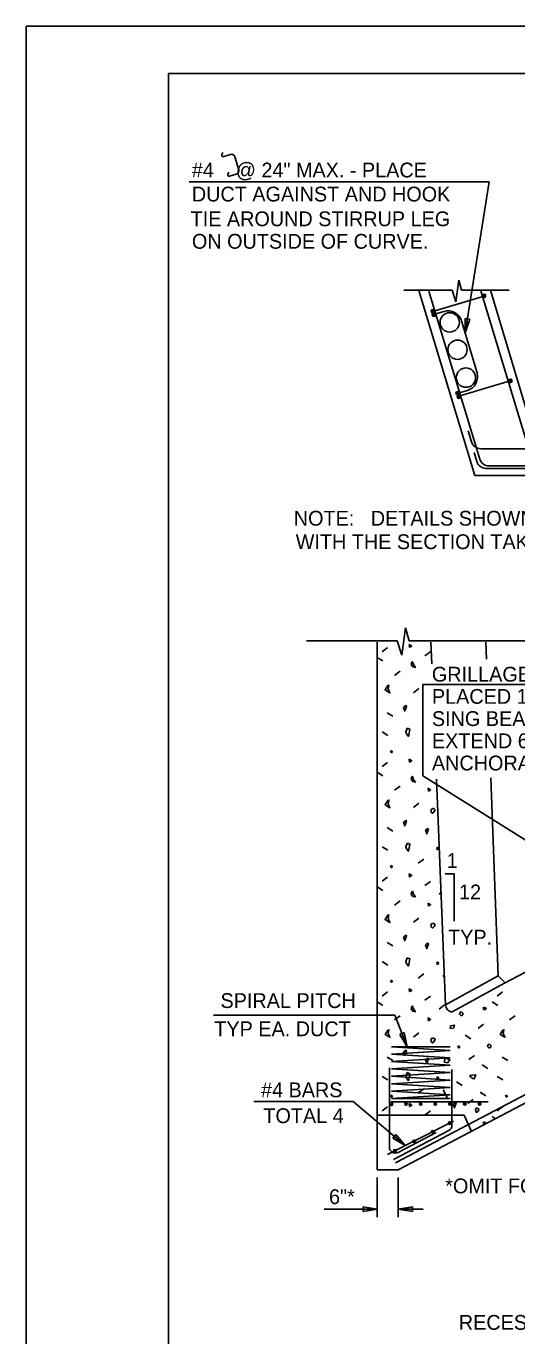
# Model space of a CAD drawing. Extents: x 0 to 22.7, y 0 to 15.7.
# Drawn here: x 0 to 3.45, y 5.45 to 14.67 of the extents above; entities that cross this region are included whole.
import ezdxf

# ---------------------------------------------------------------- set-up
doc = ezdxf.new("R2010")
doc.units = 0
for name, color, linetype in [('BORDER_ANNO_Cutsheet', 7, 'Continuous'), ('BRDG_ANNO_Anno-Sheet', 7, 'Continuous'), ('BRDG_ANNO_General-Notes', 7, 'Continuous'), ('BRDG_BASE_Dtlctrln', 7, 'Continuous'), ('BRDG_BASE_Obj-Line', 7, 'Continuous'), ('BRDG_BASE_Pattern', 7, 'Continuous'), ('BRDG_BASE_Rebar', 7, 'Continuous')]:
    doc.layers.add(name, color=color, linetype=linetype)

msp = doc.modelspace()

# ---------------------------------------------------------------- linework, layer by layer
at = {"layer": 'BORDER_ANNO_Cutsheet'}
msp.add_lwpolyline([(0, 14.6667), (22.6667, 14.6667), (22.6667, 0), (0, 0)], close=True, dxfattribs=at)
at = {"layer": 'BRDG_ANNO_Anno-Sheet'}
msp.add_lwpolyline([(1, 14.3333), (22.3333, 14.3333), (22.3333, 0.3333), (1, 0.3333)], close=True, dxfattribs=at)
at = {"layer": 'BRDG_ANNO_General-Notes'}
for p, q in [((3.2552, 13.5712), (1.147, 13.5712)), ((3.0872, 12.5074), (3.2552, 13.5712)), ((3.0863, 12.6087), (3.1193, 12.6036)), ((3.0872, 12.5074), (3.0863, 12.6087)), ((3.1193, 12.6036), (3.0872, 12.5074)), ((6.0675, 10.0336), (2.7891, 10.0336)), ((2.7891, 10.0336), (2.7891, 9.3907)), ((4.5997, 8.2579), (2.7891, 9.3907)), ((2.9479, 8.7018), (3.0094, 8.7018)), ((3.0094, 8.3667), (3.0094, 8.7018)), ((1.3162, 7.7056), (2.5928, 7.7056)), ((2.5928, 7.7056), (2.6797, 7.4839)), ((2.6277, 7.5709), (2.6587, 7.5831)), ((2.6797, 7.4839), (2.6277, 7.5709)), ((2.6587, 7.5831), (2.6797, 7.4839)), ((2.2988, 7.0975), (1.6005, 7.0975)), ((2.665, 6.788), (2.2988, 7.0975)), ((2.5779, 6.8398), (2.5994, 6.8653)), ((2.665, 6.788), (2.5779, 6.8398)), ((2.5994, 6.8653), (2.665, 6.788)), ((2.4694, 6.5646), (2.4694, 6.2837)), ((2.6161, 6.5646), (2.6161, 6.2837)), ((2.4694, 6.3399), (2.0948, 6.3399)), ((2.3694, 6.3233), (2.3694, 6.3566)), ((2.3694, 6.3566), (2.4694, 6.3399)), ((2.4694, 6.3399), (2.3694, 6.3233)), ((2.6161, 6.3399), (2.7161, 6.3566)), ((2.7909, 6.3399), (2.6161, 6.3399)), ((2.7161, 6.3233), (2.6161, 6.3399)), ((2.7161, 6.3566), (2.7161, 6.3233))]:
    msp.add_line(p, q, dxfattribs=at)
at = {"layer": 'BRDG_BASE_Dtlctrln'}
msp.add_line((2.5405, 6.7252), (3.0046, 6.9592), dxfattribs=at)
at = {"layer": 'BRDG_BASE_Obj-Line'}
for p, q in [((3.0218, 12.7276), (3.0421, 12.8803)), ((3.0421, 12.8803), (3.0627, 12.808)), ((2.9958, 12.808), (2.6553, 12.808)), ((2.7614, 12.8061), (3.1561, 11.5048)), ((2.9958, 12.808), (3.0218, 12.7276)), ((3.3959, 12.808), (3.0627, 12.808)), ((3.3192, 12.808), (3.0627, 12.808)), ((3.2652, 12.808), (3.5786, 11.7597)), ((3.1561, 11.5048), (4.3145, 11.5048)), ((2.6414, 10.2406), (2.6669, 10.4317)), ((2.6669, 10.4317), (2.6926, 10.3412)), ((2.6089, 10.3412), (1.9724, 10.3412)), ((2.4694, 6.6182), (2.4694, 10.332)), ((2.6089, 10.3412), (2.6414, 10.2406)), ((3.5639, 10.3412), (2.6926, 10.3412)), ((2.8459, 10.332), (2.8521, 10.1792)), ((3.2372, 10.2127), (3.2329, 10.3313)), ((2.885, 9.368), (2.9494, 7.779)), ((3.3196, 7.983), (3.2681, 9.3773)), ((4.8611, 8.7151), (3.3593, 7.9299)), ((2.6161, 6.6182), (6.0466, 8.4231)), ((2.9494, 7.779), (3.3184, 7.983)), ((2.996, 7.7291), (3.3593, 7.9299)), ((3.3658, 7.9356), (3.3184, 7.983)), ((2.4694, 7.0027), (3.0794, 7.0027)), ((3.0794, 7.0027), (3.1307, 6.8914)), ((2.4694, 6.6182), (2.6161, 6.6182))]:
    msp.add_line(p, q, dxfattribs=at)
for centre in [(2.9788, 12.5819), (3.0335, 12.3899), (3.0931, 12.193)]:
    msp.add_circle(centre, 0.068, dxfattribs=at)
msp.add_arc((3.0003, 7.779), 0.0509, 180.0392, 265.73939, dxfattribs=at)
at = {"layer": 'BRDG_BASE_Pattern'}
for p, q in [((2.5413, 10.2934), (2.5028, 10.2641)), ((2.843, 10.2639), (2.8045, 10.2345)), ((2.4694, 10.2241), (2.509, 10.1991)), ((2.6296, 10.1261), (2.5911, 10.0968)), ((2.7616, 10.0052), (2.7231, 9.9759)), ((2.5398, 9.8346), (2.5794, 9.8098)), ((2.5039, 9.6994), (2.5434, 9.6744)), ((2.4694, 9.4161), (2.509, 9.3911)), ((2.5413, 9.4854), (2.5028, 9.4561)), ((2.6296, 9.3182), (2.5911, 9.2889)), ((2.7616, 9.1972), (2.7231, 9.1679)), ((2.5398, 9.0267), (2.5794, 9.0018)), ((2.5039, 8.8915), (2.5434, 8.8664)), ((2.7964, 8.8045), (2.7579, 8.7752)), ((2.5413, 8.6774), (2.5028, 8.6482)), ((2.4694, 8.6082), (2.509, 8.5832)), ((2.843, 8.6479), (2.8045, 8.6186)), ((2.6296, 8.5102), (2.5911, 8.4809)), ((2.9174, 8.5677), (2.904, 8.5574)), ((2.7616, 8.3893), (2.7231, 8.36)), ((2.5398, 8.2187), (2.5794, 8.1939)), ((2.5039, 8.0835), (2.5434, 8.0584)), ((2.7964, 7.9965), (2.7579, 7.9672)), ((2.9336, 7.9876), (2.9416, 7.9716)), ((2.5413, 7.8695), (2.5028, 7.8402)), ((2.843, 7.8399), (2.8045, 7.8107)), ((3.3501, 7.8695), (3.3116, 7.8402)), ((2.4694, 7.8003), (2.509, 7.7753)), ((2.9424, 7.7787), (2.904, 7.7494)), ((3.2782, 7.8003), (3.3178, 7.7753)), ((2.6296, 7.7022), (2.5911, 7.673)), ((3.4384, 7.7022), (3.3999, 7.673)), ((2.7616, 7.5813), (2.7231, 7.552)), ((3.087, 7.5656), (3.1267, 7.5406)), ((3.2174, 7.6425), (3.179, 7.6132)), ((2.5398, 7.4107), (2.5794, 7.3859)), ((3.1526, 7.4227), (3.1141, 7.3934)), ((3.3486, 7.4107), (3.3881, 7.3859)), ((3.2077, 7.3561), (3.2473, 7.3311)), ((2.5039, 7.2755), (2.5434, 7.2505)), ((3.0276, 7.2363), (3.0672, 7.2112)), ((3.3127, 7.2755), (3.3522, 7.2505)), ((2.7964, 7.1885), (2.7579, 7.1593)), ((2.9336, 7.1797), (2.963, 7.1208)), ((3.1443, 7.1135), (3.1058, 7.0842)), ((3.1927, 7.1641), (3.2323, 7.1391)), ((2.5413, 7.0616), (2.5028, 7.0322)), ((2.843, 7.032), (2.8045, 7.0027)), ((3.3501, 7.0616), (3.3116, 7.0322)), ((3.2782, 6.9923), (3.2985, 6.9795))]:
    msp.add_line(p, q, dxfattribs=at)
for points in [[(2.6936, 10.316), (2.6966, 10.2953), (2.7114, 10.3042)], [(2.7116, 10.1906), (2.7083, 10.174), (2.7193, 10.1578), (2.7378, 10.1542), (2.723, 10.1736), (2.7167, 10.1939)], [(2.5443, 10.0255), (2.5237, 9.9947), (2.5583, 9.974), (2.5457, 10.002), (2.551, 10.0277)], [(2.6538, 9.8728), (2.6629, 9.8462), (2.6629, 9.8491), (2.6747, 9.8787), (2.6717, 9.8846)], [(2.6797, 9.7253), (2.6707, 9.6988), (2.6753, 9.6856), (2.6885, 9.6679), (2.6944, 9.6915), (2.6989, 9.718)], [(2.5665, 9.567), (2.5628, 9.5589), (2.5671, 9.5544), (2.5724, 9.5544), (2.5746, 9.5568), (2.5746, 9.5611), (2.5739, 9.5632), (2.5716, 9.5656)], [(2.6936, 9.508), (2.6966, 9.4873), (2.7114, 9.4962)], [(2.7116, 9.3827), (2.7083, 9.366), (2.7193, 9.3498), (2.7378, 9.3462), (2.723, 9.3657), (2.7167, 9.3859)], [(2.5443, 9.2176), (2.5237, 9.1867), (2.5583, 9.166), (2.5457, 9.194), (2.551, 9.2197)], [(2.8269, 9.3034), (2.8299, 9.2828), (2.8447, 9.2917)], [(2.8482, 9.157), (2.8482, 9.1347), (2.8583, 9.1275), (2.8614, 9.1304), (2.8701, 9.1393), (2.8759, 9.1511), (2.8717, 9.157), (2.8657, 9.1598), (2.8629, 9.1598), (2.8571, 9.1582)], [(2.6538, 9.0648), (2.6629, 9.0383), (2.6629, 9.0411), (2.6747, 9.0707), (2.6717, 9.0766)], [(2.8076, 9.0083), (2.8167, 8.9817), (2.8167, 8.9846), (2.8284, 9.0142), (2.8255, 9.0201)], [(2.6797, 8.9174), (2.6707, 8.8908), (2.6753, 8.8776), (2.6885, 8.8599), (2.6944, 8.8835), (2.6989, 8.9101)], [(2.888, 8.8796), (2.8904, 8.8722), (2.8925, 8.8722), (2.8955, 8.8729), (2.8977, 8.8751), (2.8998, 8.8796), (2.8992, 8.884), (2.8955, 8.8847), (2.8939, 8.8863), (2.891, 8.8863)], [(2.5665, 8.7591), (2.5628, 8.7509), (2.5671, 8.7465), (2.5724, 8.7465), (2.5746, 8.7488), (2.5746, 8.7531), (2.5739, 8.7553), (2.5716, 8.7577)], [(2.6936, 8.7001), (2.6966, 8.6794), (2.7114, 8.6883)], [(2.7116, 8.5747), (2.7083, 8.5581), (2.7193, 8.5419), (2.7378, 8.5382), (2.723, 8.5578), (2.7167, 8.578)], [(2.8269, 8.4955), (2.8299, 8.4748), (2.8447, 8.4837)], [(2.5443, 8.4096), (2.5237, 8.3788), (2.5583, 8.358), (2.5457, 8.386), (2.551, 8.4118)], [(2.8482, 8.3491), (2.8482, 8.3267), (2.8583, 8.3195), (2.8614, 8.3224), (2.8701, 8.3313), (2.8759, 8.3431), (2.8717, 8.3491), (2.8657, 8.3519), (2.8629, 8.3519), (2.8571, 8.3503)], [(2.6538, 8.2569), (2.6629, 8.2303), (2.6629, 8.2332), (2.6747, 8.2628), (2.6717, 8.2686)], [(2.8076, 8.2003), (2.8167, 8.1738), (2.8167, 8.1766), (2.8284, 8.2062), (2.8255, 8.2121)], [(2.6797, 8.1094), (2.6707, 8.0829), (2.6753, 8.0696), (2.6885, 8.0519), (2.6944, 8.0755), (2.6989, 8.1021)], [(2.888, 8.0716), (2.8904, 8.0642), (2.8925, 8.0642), (2.8955, 8.065), (2.8977, 8.0671), (2.8998, 8.0716), (2.8992, 8.076), (2.8955, 8.0768), (2.8939, 8.0783), (2.891, 8.0783)], [(2.5665, 7.9511), (2.5628, 7.943), (2.5671, 7.9385), (2.5724, 7.9385), (2.5746, 7.9408), (2.5746, 7.9452), (2.5739, 7.9473), (2.5716, 7.9497)], [(2.6936, 7.8921), (2.6966, 7.8715), (2.7114, 7.8803)], [(2.7116, 7.7668), (2.7083, 7.7502), (2.7193, 7.7339), (2.7378, 7.7303), (2.723, 7.7498), (2.7167, 7.7701)], [(3.2171, 7.7623), (3.2164, 7.7466), (3.2259, 7.7443), (3.2352, 7.755)], [(2.8269, 7.6875), (2.8299, 7.6669), (2.8447, 7.6757)], [(3.0547, 7.7291), (3.0473, 7.7129), (3.056, 7.7039), (3.0666, 7.7039), (3.0709, 7.7086), (3.0709, 7.7172), (3.0695, 7.7215), (3.0649, 7.7262)], [(2.5443, 7.6017), (2.5237, 7.5708), (2.5583, 7.5501), (2.5457, 7.5781), (2.551, 7.6038)], [(2.9852, 7.6302), (2.9822, 7.6126), (3.0029, 7.6155), (3.0087, 7.6184), (3.0117, 7.6361)], [(3.3531, 7.6017), (3.3325, 7.5708), (3.3671, 7.5501), (3.3545, 7.5781), (3.3598, 7.6038)], [(2.8482, 7.5411), (2.8482, 7.5187), (2.8583, 7.5116), (2.8614, 7.5145), (2.8701, 7.5233), (2.8759, 7.5352), (2.8717, 7.5411), (2.8657, 7.5439), (2.8629, 7.5439), (2.8571, 7.5423)], [(3.04, 7.4896), (3.0363, 7.4815), (3.0406, 7.477), (3.0459, 7.477), (3.0481, 7.4793), (3.0481, 7.4836), (3.0473, 7.4858), (3.0451, 7.4881)], [(3.2516, 7.5021), (3.2442, 7.4859), (3.2528, 7.4769), (3.2634, 7.4769), (3.2678, 7.4816), (3.2678, 7.4903), (3.2663, 7.4945), (3.2617, 7.4993)], [(2.6538, 7.449), (2.6629, 7.4223), (2.6629, 7.4252), (2.6747, 7.4548), (2.6717, 7.4607)], [(2.8076, 7.3924), (2.8167, 7.3658), (2.8167, 7.3686), (2.8284, 7.3983), (2.8255, 7.4042)], [(2.9446, 7.4065), (2.9432, 7.3748), (2.9623, 7.3703), (2.9807, 7.3917)], [(2.6797, 7.3015), (2.6707, 7.2749), (2.6753, 7.2617), (2.6885, 7.244), (2.6944, 7.2676), (2.6989, 7.2941)], [(3.1394, 7.2839), (3.1218, 7.2824), (3.1218, 7.2736), (3.1409, 7.2604), (3.1513, 7.2589), (3.1616, 7.2868)], [(2.888, 7.2636), (2.8904, 7.2562), (2.8925, 7.2562), (2.8955, 7.257), (2.8977, 7.2592), (2.8998, 7.2636), (2.8992, 7.2681), (2.8955, 7.2688), (2.8939, 7.2704), (2.891, 7.2704)], [(2.5665, 7.1431), (2.5628, 7.1351), (2.5671, 7.1305), (2.5724, 7.1305), (2.5746, 7.1329), (2.5746, 7.1372), (2.5739, 7.1394), (2.5716, 7.1417)], [(3.3753, 7.1431), (3.3716, 7.1351), (3.3759, 7.1305), (3.3812, 7.1305), (3.3834, 7.1329), (3.3834, 7.1372), (3.3827, 7.1394), (3.3804, 7.1417)], [(2.6936, 7.0842), (2.6966, 7.0635), (2.7114, 7.0724)], [(3.0024, 7.0798), (3.0116, 7.0532), (3.0116, 7.0561), (3.0233, 7.0857), (3.0203, 7.0916)], [(3.1597, 7.0384), (3.1644, 7.0237), (3.1686, 7.0237), (3.1746, 7.0252), (3.179, 7.0295), (3.1833, 7.0384), (3.1821, 7.0472), (3.1746, 7.0488), (3.1715, 7.0518), (3.1656, 7.0518)]]:
    msp.add_lwpolyline(points, close=True, dxfattribs=at)
for points in [[(3.2171, 6.9544), (3.2164, 6.9386), (3.2193, 6.9379)], [(3.2339, 6.9456), (3.2352, 6.947), (3.2171, 6.9544)]]:
    msp.add_lwpolyline(points, dxfattribs=at)
at = {"layer": 'BRDG_BASE_Rebar'}
for p, q in [((1.3841, 13.7781), (1.3764, 13.7629)), ((1.3894, 13.75), (1.4363, 13.764)), ((1.4674, 13.7472), (1.4947, 13.656)), ((1.4246, 13.6389), (1.4181, 13.6239)), ((1.4779, 13.6249), (1.431, 13.6109)), ((2.8322, 12.8021), (3.1912, 11.6189)), ((2.859, 12.6593), (3.2287, 12.7699)), ((3.1968, 12.8034), (3.5511, 11.6355)), ((2.8652, 12.6381), (2.9372, 12.6596)), ((3.0617, 12.5925), (3.1707, 12.228)), ((3.0431, 12.0637), (3.4031, 12.1714)), ((3.1035, 12.1035), (3.0381, 12.0839)), ((3.1095, 11.8176), (3.1329, 11.7404)), ((3.1506, 11.6663), (3.1701, 11.6021)), ((3.1967, 11.6931), (4.3134, 11.6931)), ((3.2339, 11.5548), (4.3134, 11.5548)), ((3.2549, 11.5715), (4.3137, 11.5715)), ((2.5968, 6.6661), (6.0472, 8.4816)), ((2.5682, 7.4839), (2.981, 7.4839)), ((2.981, 7.4579), (2.5682, 7.4839)), ((2.5682, 7.4318), (2.981, 7.4579)), ((2.981, 7.4058), (2.5682, 7.4318)), ((2.5682, 7.3797), (2.981, 7.4058)), ((2.981, 7.3537), (2.5682, 7.3797)), ((2.5545, 6.7771), (2.5545, 7.3354)), ((2.5682, 7.3277), (2.981, 7.3537)), ((2.981, 7.3016), (2.5682, 7.3277)), ((2.5682, 7.2756), (2.981, 7.3016)), ((2.9946, 6.9306), (2.9946, 7.3245)), ((2.981, 7.2495), (2.5682, 7.2756)), ((2.5682, 7.2235), (2.981, 7.2495)), ((2.981, 7.1974), (2.5682, 7.2235)), ((2.5682, 7.1714), (2.981, 7.1974)), ((2.981, 7.1454), (2.5682, 7.1714)), ((2.5682, 7.1193), (2.981, 7.1454)), ((2.5682, 7.1193), (2.981, 7.1193)), ((2.5639, 7.0956), (2.5639, 7.0956)), ((2.5639, 7.0956), (3.2482, 7.0956)), ((2.5844, 6.6896), (2.9723, 6.8937)), ((2.6156, 6.7402), (2.8828, 6.8808))]:
    msp.add_line(p, q, dxfattribs=at)
for centre, radius in [((3.2199, 12.769), 0.0125), ((3.2199, 12.769), 0.00833), ((3.2199, 12.769), 0.00417), ((2.8599, 12.6598), 0.0125), ((2.8599, 12.6598), 0.00833), ((2.8671, 12.6356), 0.0125), ((2.8599, 12.6598), 0.00417), ((2.8671, 12.6356), 0.00833), ((2.8671, 12.6356), 0.00417), ((3.4053, 12.1707), 0.0125), ((3.4053, 12.1707), 0.00833), ((3.4053, 12.1707), 0.00417), ((3.0354, 12.0836), 0.0125), ((3.0354, 12.0836), 0.00833), ((3.0354, 12.0836), 0.00417), ((3.0426, 12.0598), 0.0125), ((3.0426, 12.0598), 0.00833), ((3.0426, 12.0598), 0.00417), ((2.5687, 7.0799), 0.0089), ((2.5687, 7.0799), 0.00593), ((2.5687, 7.0799), 0.00297), ((2.6717, 7.0805), 0.0089), ((2.6717, 7.0805), 0.00593), ((2.6717, 7.0805), 0.00297), ((2.7746, 7.081), 0.0089), ((2.7746, 7.081), 0.00593), ((2.7746, 7.081), 0.00297), ((2.8775, 7.0815), 0.0089), ((2.8775, 7.0815), 0.00593), ((2.8775, 7.0815), 0.00297), ((2.9805, 7.0821), 0.0089), ((2.9805, 7.0821), 0.00593), ((2.9805, 7.0821), 0.00297), ((3.0846, 7.0821), 0.0089), ((3.0846, 7.0821), 0.00593), ((3.0846, 7.0821), 0.00297), ((3.1888, 7.0821), 0.0089), ((3.1888, 7.0821), 0.00593), ((3.1888, 7.0821), 0.00297), ((2.9783, 6.9461), 0.0089), ((2.9783, 6.9461), 0.00593), ((2.9783, 6.9461), 0.00297), ((2.7287, 6.8184), 0.0089), ((2.7287, 6.8184), 0.00593), ((2.7287, 6.8184), 0.00297), ((2.8584, 6.8855), 0.0089), ((2.8584, 6.8855), 0.00593), ((2.8584, 6.8855), 0.00297), ((2.5925, 6.7514), 0.0089), ((2.5925, 6.7514), 0.00593), ((2.5925, 6.7514), 0.00297)]:
    msp.add_circle(centre, radius, dxfattribs=at)
for centre, radius, start, end in [((1.3864, 13.7599), 0.0104, 163.35109, 286.65044), ((1.4435, 13.74), 0.025, 16.65, 106.65), ((1.4707, 13.6489), 0.025, 286.65, 16.65), ((1.4281, 13.6209), 0.0104, 163.35109, 286.68295), ((2.9659, 12.5639), 0.1, 16.65, 106.65), ((3.0749, 12.1993), 0.1, 286.65, 16.65), ((3.1967, 11.7597), 0.0667, 196.86846, 270), ((3.255, 11.6382), 0.0667, 196.87338, 270), ((3.2339, 11.6215), 0.0667, 196.87794, 270), ((2.9529, 6.9306), 0.0417, 297.74896, 0), ((2.5962, 6.7771), 0.0417, 180, 297.75176)]:
    msp.add_arc(centre, radius, start, end, dxfattribs=at)

# ---------------------------------------------------------------- texts
at = {"layer": 'BRDG_ANNO_General-Notes'}
for s, height, p in [('#4    @ 24" MAX. - PLACE', 0.104115, (1.1648, 13.6023)), ('DUCT AGAINST AND HOOK', 0.104115, (1.1651, 13.433)), ('TIE AROUND STIRRUP LEG', 0.104115, (1.1565, 13.2588)), ('ON OUTSIDE OF CURVE.', 0.104115, (1.1658, 13.1005)), ('NOTE:   DETAILS SHOWN ARE FOR A CURVE TO THE RIGHT', 0.104115, (1.8821, 11.1514)), ('WITH THE SECTION TAKEN LOOKING AHEAD ON STATION.', 0.104115, (1.8957, 10.9862)), ('GRILLAGE - #4 @ 4" BOTH WAYS,  TO BE', 0.104167, (2.8535, 10.0537)), ('PLACED 1" MAX. CLEAR FROM PRESTRES-', 0.104167, (2.8535, 9.8974)), ('SING BEARING PLATE AT EACH GIRDER.', 0.104167, (2.8535, 9.7412)), ('EXTEND 6" BEYOND RECESS FOR', 0.104167, (2.8535, 9.5849)), ('ANCHORAGE.', 0.10417, (2.8535, 9.4287)), ('1', 0.1042, (2.9576, 8.7428)), ('12', 0.10417, (3.0443, 8.521)), ('TYP.', 0.10417, (2.9672, 8.2028)), ('SPIRAL PITCH', 0.104115, (1.3666, 7.7565)), ('TYP EA. DUCT', 0.104115, (1.3234, 7.5581)), ('#4 BARS', 0.10411, (1.6517, 7.1283)), ('TOTAL 4', 0.10411, (1.6681, 6.9465)), ('*OMIT FOR SKEW >20', 0.104115, (2.9474, 6.4523)), ('6"*', 0.10411, (2.1298, 6.3765)), ('RECESS FOR ANCHORAGE SHALL BE', 0.104167, (3.0429, 5.4917))]:
    msp.add_text(s, height=height, dxfattribs=at).set_placement(p)

doc.saveas('drawing.dxf')
